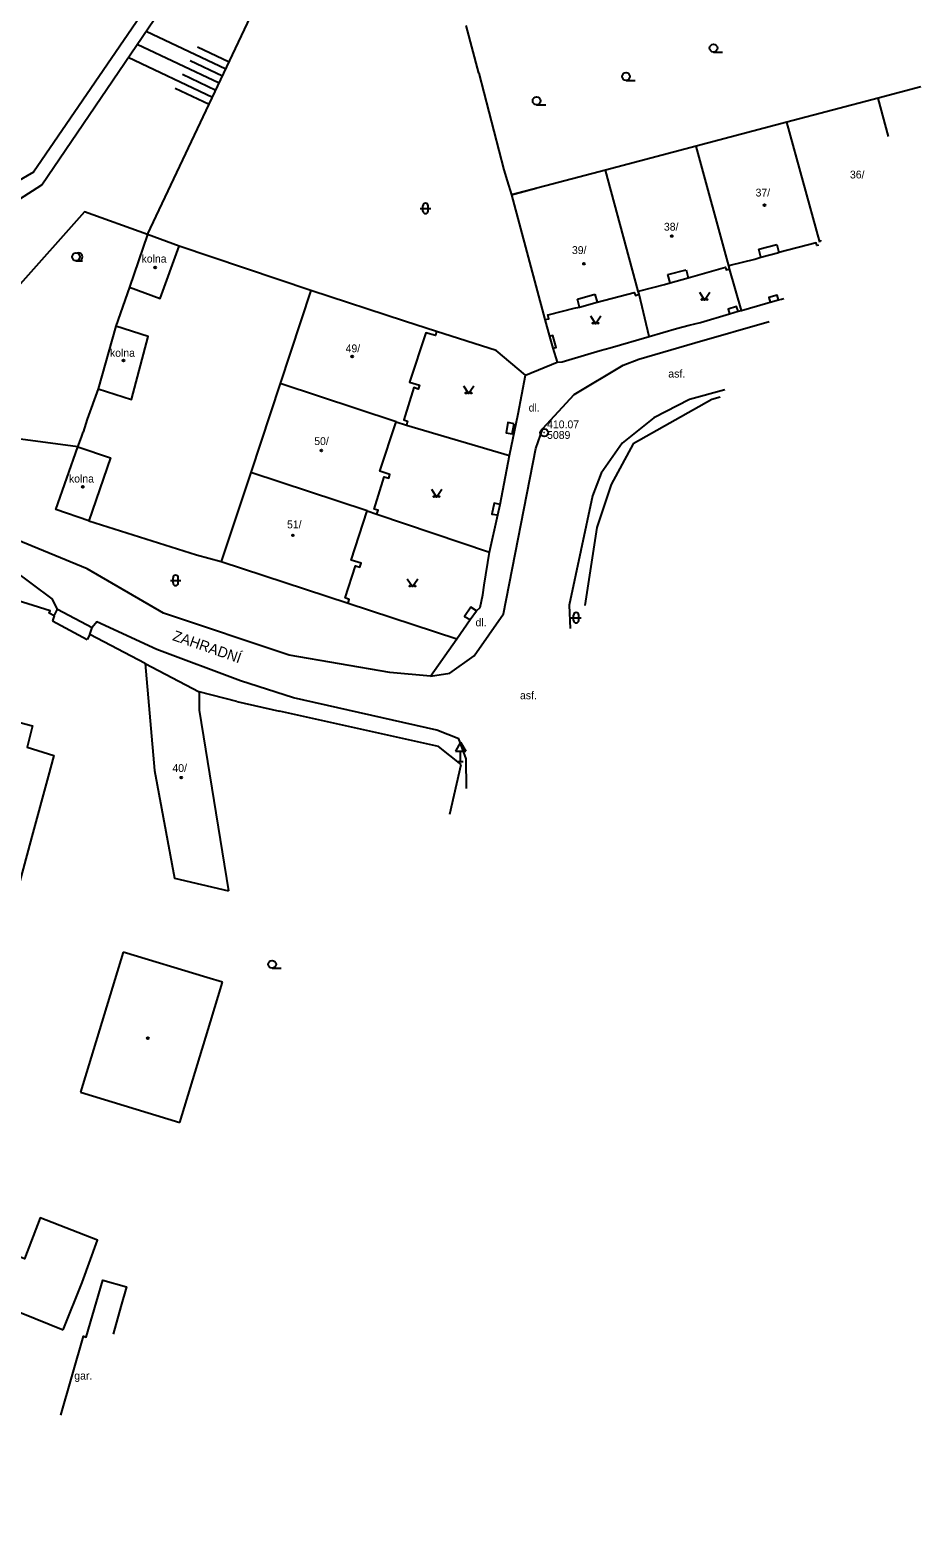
# Model space of a CAD drawing. Extents: x -737488 to -734267, y -1145775 to -1142573.
# Drawn here: x -736865.1 to -736779.7, y -1144915.2 to -1144770.7 of the extents above; entities that cross this region are included whole.
import ezdxf

# ---------------------------------------------------------------- set-up
doc = ezdxf.new("R2010")
doc.units = 0
for name, color, linetype in [('Vrstva 1', 7, 'Continuous'), ('Vrstva 10', 7, 'Continuous'), ('Vrstva 11', 7, 'Continuous'), ('Vrstva 12', 7, 'Continuous'), ('Vrstva 13', 7, 'Continuous'), ('Vrstva 14', 7, 'Continuous'), ('Vrstva 19', 7, 'Continuous'), ('Vrstva 3', 7, 'Continuous'), ('Vrstva 4', 7, 'Continuous'), ('Vrstva 5', 7, 'Continuous'), ('Vrstva 6', 7, 'Continuous'), ('Vrstva 8', 7, 'Continuous'), ('Vrstva 9', 7, 'Continuous')]:
    doc.layers.add(name, color=color, linetype=linetype)

# ---------------------------------------------------------------- blocks, each defined once
blk = doc.blocks.new('1.079')
at = {"layer": 'Vrstva 1'}
for radius in [0.75, 0.001]:
    blk.add_circle((0, -0.001), radius, dxfattribs=at)
blk = doc.blocks.new('3.040')
at = {"layer": 'Vrstva 1'}
blk.add_line((0, -0.75), (1.75, -0.75), dxfattribs=at)
blk.add_circle((0, 0), 0.75, dxfattribs=at)
blk = doc.blocks.new('3.110')
at = {"layer": 'Vrstva 1'}
blk.add_line((0, -0.75), (1.25, -0.75), dxfattribs=at)
blk.add_circle((0, 0), 0.75, dxfattribs=at)
blk.add_arc((0.5, 0), 0.75, 249.4944, 109.0474, dxfattribs=at)
blk = doc.blocks.new('3.140')
at = {"layer": 'Vrstva 1'}
blk.add_lwpolyline([(-1, 1.5), (0, 0), (1, 1.5)], dxfattribs=at)
for centre in [(-0.5, 0.1), (0.5, 0.1)]:
    blk.add_circle(centre, 0.1, dxfattribs=at)
blk = doc.blocks.new('3.160')
at = {"layer": 'Vrstva 1'}
for p, q in [((-1, 0), (1, 0)), ((-0.5, -0.5), (-0.5, 0.5)), ((0.5, -0.5), (0.5, 0.5))]:
    blk.add_line(p, q, dxfattribs=at)
for centre, start, end in [((0, 0.5), 0, 180), ((0, -0.5), 180, 360)]:
    blk.add_arc(centre, 0.5, start, end, dxfattribs=at)
blk = doc.blocks.new('4.020')
at = {"layer": 'Vrstva 1'}
blk.add_circle((0, 0), 0.175, dxfattribs=at)
blk = doc.blocks.new('5.270')
at = {"layer": 'Vrstva 1'}
for p, q in [((0, 3.732), (-1, 2)), ((0, 3.732), (1, 2)), ((-1, 2), (1, 2)), ((-0.5, 0), (0.5, 0)), ((0, 0), (0, 2))]:
    blk.add_line(p, q, dxfattribs=at)

msp = doc.modelspace()

# ---------------------------------------------------------------- linework, layer by layer
at = {"layer": 'Vrstva 10'}
for points in [[(-737157.23, -1144612.91), (-737139.97, -1144630.07), (-737087.28, -1144684.25), (-737074.24, -1144695.65), (-737061.32, -1144701.82), (-737047.37, -1144710.31), (-737029.75, -1144716.98), (-737014.23, -1144719.82), (-736985.3, -1144724.31), (-736947.36, -1144728.54), (-736914.56, -1144733.34), (-736885.96, -1144736.43), (-736848.96, -1144741.06), (-736841.09, -1144741.37), (-736845.82, -1144755.24), (-736853.37, -1144767.68), (-736864.78, -1144784.35), (-736886.96, -1144797.2)], [(-736885.77, -1144799.53), (-736863.97, -1144785.57), (-736852.06, -1144768.02), (-736845.63, -1144757.82), (-736839.46, -1144741.72), (-736833.85, -1144740.76), (-736819.77, -1144737.85)], [(-736826.72, -1144832.66), (-736824.85, -1144832.36), (-736822.52, -1144830.71), (-736819.71, -1144826.67), (-736816.62, -1144810.84), (-736815.93, -1144808.92), (-736812.95, -1144805.66), (-736808.25, -1144802.83), (-736806.75, -1144802.26), (-736801.36, -1144800.69), (-736794.25, -1144798.65)], [(-736817.6, -1144803.79), (-736814.58, -1144802.55)], [(-736798.5, -1144805.21), (-736801.89, -1144806.15), (-736805.31, -1144807.89), (-736808.33, -1144810.32), (-736810.35, -1144813.2), (-736811.19, -1144815.38), (-736813.4, -1144825.86), (-736813.32, -1144828.08)], [(-736826.72, -1144832.66), (-736830.61, -1144832.31), (-736840.28, -1144830.64), (-736852.33, -1144826.62), (-736859.62, -1144822.37), (-736874.24, -1144816.36), (-736880.96, -1144815.92)], [(-736862.48, -1144826.23), (-736862.98, -1144825.23), (-736866.76, -1144822.43), (-736874.46, -1144819.59), (-736880.16, -1144818.92), (-736884.21, -1144819.43), (-736894.52, -1144823.06), (-736901.86, -1144830.06), (-736906.51, -1144840.28), (-736908.98, -1144850.82), (-736911.51, -1144865.17), (-736912.91, -1144881.09), (-736910.68, -1144885.98), (-736901.74, -1144895.69), (-736893.29, -1144902.9), (-736886.85, -1144907.19), (-736879.51, -1144911.23), (-736869.79, -1144915.23)], [(-736862.79, -1144826.86), (-736862.48, -1144826.23)], [(-736862.48, -1144826.23), (-736859.17, -1144827.99)], [(-736859.38, -1144828.65), (-736859.17, -1144827.99)], [(-736823.26, -1144843.42), (-736823.29, -1144840.58), (-736823.99, -1144838.65), (-736826.11, -1144837.82), (-736839.86, -1144834.72), (-736844.94, -1144833.11), (-736852.96, -1144830.08), (-736858.7, -1144827.43), (-736859.17, -1144827.99)], [(-736826.72, -1144832.66), (-736824.19, -1144829.08)]]:
    msp.add_lwpolyline(points, dxfattribs=at)
at = {"layer": 'Vrstva 11'}
msp.add_lwpolyline([(-736860.53, -1144810.66), (-736881.41, -1144807.88), (-736885.77, -1144800.79)], dxfattribs=at)
at = {"layer": 'Vrstva 12'}
for points in [[(-736853.84, -1144790.33), (-736842.01, -1144765.32), (-736835.71, -1144748.55), (-736834.5, -1144742.96), (-736819.77, -1144737.85)], [(-736846.34, -1144774.47), (-736853.99, -1144770.86)], [(-736847.62, -1144777.19), (-736855.69, -1144773.37)], [(-736846.98, -1144775.83), (-736854.84, -1144772.11)], [(-736846.02, -1144773.8), (-736849.04, -1144772.37)], [(-736846.66, -1144775.15), (-736849.76, -1144773.69)], [(-736847.3, -1144776.51), (-736850.49, -1144775)], [(-736847.94, -1144777.86), (-736851.21, -1144776.32)], [(-736853.84, -1144790.33), (-736859.89, -1144788.14), (-736866.31, -1144795.38), (-736885.77, -1144800.79)]]:
    msp.add_lwpolyline(points, dxfattribs=at)
at = {"layer": 'Vrstva 4'}
for points in [[(-736818.95, -1144786.52), (-736815.75, -1144798.47)], [(-736853.84, -1144790.33), (-736855.58, -1144795.37)], [(-736850.81, -1144791.43), (-736853.84, -1144790.33)], [(-736855.58, -1144795.37), (-736852.63, -1144796.44), (-736850.81, -1144791.43)], [(-736795.23, -1144791.73), (-736793.5, -1144791.28)], [(-736795.03, -1144792.5), (-736795.23, -1144791.73)], [(-736795.03, -1144792.5), (-736793.3, -1144792.05)], [(-736793.5, -1144791.28), (-736793.3, -1144792.05)], [(-736789.51, -1144791.33), (-736789.67, -1144791.37), (-736789.74, -1144791.11), (-736793.3, -1144792.05)], [(-736789.41, -1144790.93), (-736789.26, -1144790.89), (-736789.22, -1144790.88)], [(-736789.37, -1144791.1), (-736789.41, -1144790.93)], [(-736802.01, -1144794.49), (-736798.42, -1144793.46), (-736798.36, -1144793.71), (-736798.04, -1144793.61)], [(-736798.12, -1144793.32), (-736797.97, -1144793.27), (-736795.61, -1144792.67), (-736795.03, -1144792.5)], [(-736798.04, -1144793.61), (-736798.12, -1144793.32)], [(-736806.79, -1144795.75), (-736806.64, -1144795.71), (-736804.28, -1144795.1), (-736803.74, -1144794.94)], [(-736803.94, -1144794.17), (-736802.21, -1144793.72)], [(-736803.74, -1144794.94), (-736803.94, -1144794.17)], [(-736803.74, -1144794.94), (-736802.01, -1144794.49)], [(-736802.21, -1144793.72), (-736802.01, -1144794.49)], [(-736838.19, -1144795.68), (-736841.14, -1144804.61)], [(-736826.13, -1144799.62), (-736829.19, -1144798.63), (-736838.19, -1144795.68)], [(-736812.63, -1144796.52), (-736810.95, -1144796.05)], [(-736812.41, -1144797.29), (-736812.63, -1144796.52)], [(-736810.95, -1144796.05), (-736810.73, -1144796.82)], [(-736810.73, -1144796.82), (-736807.17, -1144795.88), (-736807.04, -1144796.16), (-736806.71, -1144796.05)], [(-736806.71, -1144796.05), (-736806.79, -1144795.75)], [(-736815.75, -1144798.47), (-736815.36, -1144798.39), (-736815.46, -1144798.02), (-736815.31, -1144797.98), (-736812.94, -1144797.39), (-736812.41, -1144797.29)], [(-736812.41, -1144797.29), (-736810.73, -1144796.82)], [(-736826.13, -1144799.62), (-736826.22, -1144799.99), (-736827.17, -1144799.74), (-736828.72, -1144804.46), (-736827.77, -1144804.77), (-736827.88, -1144805.13), (-736828.32, -1144805), (-736829.28, -1144808.09), (-736828.93, -1144808.22), (-736829.02, -1144808.58)], [(-736841.14, -1144804.61), (-736843.95, -1144813.13)], [(-736831.86, -1144817.12), (-736831.72, -1144816.74), (-736832.12, -1144816.63), (-736831.16, -1144813.54), (-736830.72, -1144813.67), (-736830.61, -1144813.31), (-736831.56, -1144813), (-736830, -1144808.26)], [(-736830, -1144808.26), (-736829.02, -1144808.58)], [(-736859.49, -1144817.77), (-736862.63, -1144816.69), (-736860.53, -1144810.66)], [(-736860.53, -1144810.66), (-736857.41, -1144811.73), (-736859.49, -1144817.77)], [(-736843.95, -1144813.13), (-736846.77, -1144821.66)], [(-736834.62, -1144825.64), (-736834.51, -1144825.29), (-736834.88, -1144825.15), (-736833.92, -1144822.06), (-736833.48, -1144822.19), (-736833.37, -1144821.83), (-736834.32, -1144821.52), (-736832.77, -1144816.8)], [(-736832.77, -1144816.8), (-736831.86, -1144817.12)], [(-736846.77, -1144821.66), (-736834.62, -1144825.64)], [(-736854.07, -1144831.42), (-736848.88, -1144834.14)]]:
    msp.add_lwpolyline(points, dxfattribs=at)
at = {"layer": 'Vrstva 5'}
for points in [[(-736779.69, -1144776.17), (-736783.79, -1144777.25), (-736792.54, -1144779.56), (-736801.23, -1144781.85), (-736809.92, -1144784.14), (-736818.95, -1144786.52)], [(-736782.78, -1144780.94), (-736783.79, -1144777.25)], [(-736789.41, -1144790.93), (-736792.54, -1144779.56)], [(-736798.12, -1144793.32), (-736801.23, -1144781.85)], [(-736806.79, -1144795.75), (-736809.92, -1144784.14)], [(-736818.95, -1144786.52), (-736816.57, -1144785.88)], [(-736856.88, -1144799.12), (-736858.58, -1144805.1), (-736855.38, -1144806.14), (-736853.8, -1144800.1), (-736856.88, -1144799.12)], [(-736830, -1144808.26), (-736841.14, -1144804.61)], [(-736832.77, -1144816.8), (-736843.95, -1144813.13)], [(-736854.07, -1144831.42), (-736853.19, -1144841.68), (-736851.27, -1144852.02), (-736846.07, -1144853.23)], [(-736872.15, -1144835.37), (-736871.5, -1144835.55), (-736865.95, -1144837.12), (-736864.89, -1144837.42), (-736865.4, -1144839.44), (-736862.82, -1144840.24), (-736863.37, -1144842.28), (-736864.93, -1144848.02), (-736867.19, -1144856.35), (-736876.92, -1144853.35), (-736873.4, -1144840.07), (-736872.15, -1144835.37)], [(-736848.88, -1144834.14), (-736848.9, -1144835.92), (-736846.07, -1144853.23)], [(-736856.17, -1144859.1), (-736860.26, -1144872.53)], [(-736848.17, -1144861.54), (-736856.17, -1144859.1)], [(-736846.67, -1144861.99), (-736848.17, -1144861.54)], [(-736847.82, -1144865.77), (-736846.67, -1144861.99)], [(-736850.76, -1144875.42), (-736847.82, -1144865.77)], [(-736860.26, -1144872.53), (-736850.76, -1144875.42)], [(-736861.95, -1144895.29), (-736860.12, -1144890.75), (-736858.65, -1144886.71), (-736864.13, -1144884.55), (-736865.64, -1144888.49), (-736879.29, -1144883.01), (-736881.03, -1144887.59), (-736879.28, -1144888.3), (-736875.65, -1144889.76), (-736872.71, -1144890.95), (-736861.95, -1144895.29)], [(-736862.16, -1144903.46), (-736860, -1144895.89), (-736859.72, -1144896.01), (-736858.12, -1144890.54), (-736855.87, -1144891.17), (-736856.4, -1144893.06), (-736857.13, -1144895.7)]]:
    msp.add_lwpolyline(points, dxfattribs=at)
at = {"layer": 'Vrstva 9'}
for points in [[(-736822.08, -1144774.86), (-736823.29, -1144770.3)], [(-736822.08, -1144774.86), (-736819.68, -1144784.13)], [(-736819.68, -1144784.13), (-736819.36, -1144785.18)], [(-736819.36, -1144785.18), (-736818.95, -1144786.52)], [(-736838.19, -1144795.68), (-736850.81, -1144791.43)], [(-736796.88, -1144797.6), (-736798.04, -1144793.61)], [(-736855.58, -1144795.37), (-736856.88, -1144799.12)], [(-736805.74, -1144800.11), (-736806.71, -1144796.05)], [(-736793.33, -1144796.59), (-736793.47, -1144796.13), (-736794.27, -1144796.37), (-736794.14, -1144796.8)], [(-736793.33, -1144796.59), (-736793.05, -1144796.53)], [(-736793.05, -1144796.53), (-736792.84, -1144796.46)], [(-736800.83, -1144798.76), (-736798.03, -1144797.92)], [(-736797.22, -1144797.67), (-736797.36, -1144797.22), (-736798.17, -1144797.48), (-736798.03, -1144797.92)], [(-736798.03, -1144797.92), (-736797.22, -1144797.67)], [(-736797.22, -1144797.67), (-736796.88, -1144797.6)], [(-736796.88, -1144797.6), (-736794.35, -1144796.87)], [(-736794.35, -1144796.87), (-736794.14, -1144796.8)], [(-736794.14, -1144796.8), (-736793.33, -1144796.59)], [(-736815.75, -1144798.47), (-736815.3, -1144800.1)], [(-736805.74, -1144800.11), (-736803.13, -1144799.33)], [(-736803.13, -1144799.33), (-736801.92, -1144799)], [(-736801.92, -1144799), (-736800.83, -1144798.76)], [(-736817.6, -1144803.79), (-736820.41, -1144801.43), (-736826.13, -1144799.62)], [(-736814.98, -1144801.23), (-736814.66, -1144801.14), (-736814.98, -1144800.01), (-736815.3, -1144800.1)], [(-736815.3, -1144800.1), (-736814.98, -1144801.23)], [(-736809.47, -1144801.17), (-736805.74, -1144800.11)], [(-736814.98, -1144801.23), (-736814.58, -1144802.55)], [(-736814.09, -1144802.51), (-736811.61, -1144801.8)], [(-736811.61, -1144801.8), (-736810.44, -1144801.45)], [(-736810.44, -1144801.45), (-736809.47, -1144801.17)], [(-736814.58, -1144802.55), (-736814.09, -1144802.51)], [(-736858.58, -1144805.1), (-736859.64, -1144808.01)], [(-736818.3, -1144807.51), (-736817.6, -1144803.79)], [(-736798.95, -1144805.9), (-736799.74, -1144806.12), (-736807.28, -1144810.38), (-736809.4, -1144814.28), (-736810.77, -1144818.39), (-736811.9, -1144825.89)], [(-736859.64, -1144808.01), (-736860.02, -1144809.27)], [(-736819.14, -1144811.5), (-736818.3, -1144807.51)], [(-736860.17, -1144809.73), (-736860.02, -1144809.27)], [(-736829.02, -1144808.58), (-736819.14, -1144811.5)], [(-736818.69, -1144808.48), (-736819.29, -1144808.33), (-736819.47, -1144809.33), (-736818.89, -1144809.42), (-736818.69, -1144808.48)], [(-736860.53, -1144810.66), (-736860.17, -1144809.73)], [(-736820.03, -1144816.19), (-736819.14, -1144811.5)], [(-736820.03, -1144816.19), (-736820.6, -1144816.07), (-736820.83, -1144817.11), (-736820.25, -1144817.19)], [(-736820.25, -1144817.19), (-736820.03, -1144816.19)], [(-736859.49, -1144817.77), (-736849.16, -1144821.02)], [(-736831.86, -1144817.12), (-736821.07, -1144820.78)], [(-736821.07, -1144820.78), (-736820.25, -1144817.19)], [(-736849.16, -1144821.02), (-736846.77, -1144821.66)], [(-736821.57, -1144823.92), (-736821.07, -1144820.78)], [(-736862.79, -1144826.86), (-736863.29, -1144826.62), (-736863.19, -1144826.38), (-736880.04, -1144821.13), (-736889.1, -1144821.66)], [(-736821.69, -1144824.87), (-736821.57, -1144823.92)], [(-736821.96, -1144826.08), (-736821.69, -1144824.87)], [(-736862.79, -1144826.86), (-736862.97, -1144827.34)], [(-736834.62, -1144825.64), (-736824.19, -1144829.08)], [(-736822.31, -1144826.4), (-736822.85, -1144826.04), (-736823.44, -1144826.92), (-736822.9, -1144827.22)], [(-736822.9, -1144827.22), (-736822.31, -1144826.4)], [(-736822.31, -1144826.4), (-736821.96, -1144826.08)], [(-736862.97, -1144827.34), (-736859.65, -1144829.13)], [(-736824.19, -1144829.08), (-736822.9, -1144827.22)], [(-736859.38, -1144828.65), (-736859.65, -1144829.13)], [(-736854.07, -1144831.42), (-736859.38, -1144828.65)], [(-736845.28, -1144835.07), (-736848.88, -1144834.14)], [(-736845.28, -1144835.07), (-736841.18, -1144835.99)], [(-736823.77, -1144841.11), (-736825.94, -1144839.4), (-736841.18, -1144835.99)], [(-736824.85, -1144845.87), (-736823.77, -1144841.11)]]:
    msp.add_lwpolyline(points, dxfattribs=at)

# ---------------------------------------------------------------- block references
at = {"layer": 'Vrstva 1', "xscale": 0.5, "yscale": 0.5}
msp.add_blockref('1.079', (-736815.81, -1144809.31), dxfattribs=at)
at = {"layer": 'Vrstva 3', "xscale": 0.5, "yscale": 0.5}
for name, p in [('3.040', (-736799.58, -1144772.46)), ('3.040', (-736807.96, -1144775.18)), ('3.040', (-736816.54, -1144777.51)), ('3.160', (-736827.19, -1144787.82)), ('3.110', (-736860.71, -1144792.46)), ('3.140', (-736800.43, -1144796.6)), ('3.140', (-736810.88, -1144798.88)), ('3.140', (-736823.06, -1144805.56)), ('3.140', (-736826.13, -1144815.49)), ('3.160', (-736851.15, -1144823.47)), ('3.140', (-736828.44, -1144824.07)), ('3.160', (-736812.75, -1144827.05)), ('3.040', (-736841.9, -1144860.26))]:
    msp.add_blockref(name, p, dxfattribs=at)
at = {"layer": 'Vrstva 8', "xscale": 0.5, "yscale": 0.5}
for p in [(-736794.68, -1144787.51), (-736803.58, -1144790.47), (-736853.11, -1144793.48), (-736812, -1144793.12), (-736856.15, -1144802.39), (-736834.23, -1144802.01), (-736837.18, -1144811.02), (-736860.06, -1144814.5), (-736839.9, -1144819.15), (-736850.61, -1144842.37), (-736853.81, -1144867.34)]:
    msp.add_blockref('4.020', p, dxfattribs=at)
at = {"layer": 'Vrstva 9', "xscale": 0.5, "yscale": 0.5}
msp.add_blockref('5.270', (-736823.82, -1144840.83), dxfattribs=at)

# ---------------------------------------------------------------- texts
at = {"layer": 'Vrstva 13'}
msp.add_text('ZAHRADNÍ', height=1, rotation=340.84, dxfattribs=at).set_placement((-736851.52, -1144829.18))
at = {"layer": 'Vrstva 14'}
for s, p in [('kolna', (-736854.42, -1144793.01)), ('kolna', (-736857.45, -1144802.04)), ('asf.', (-736803.91, -1144804.03)), ('dl.', (-736817.3, -1144807.29)), ('kolna', (-736861.38, -1144814.09)), ('dl.', (-736822.4, -1144827.87)), ('asf.', (-736818.13, -1144834.86)), ('gar.', (-736860.87, -1144900.06))]:
    msp.add_text(s, height=0.75, dxfattribs=at).set_placement(p)
at = {"layer": 'Vrstva 19'}
for s, p in [(' 410.07', (-736815.81, -1144808.89)), (' 5089', (-736815.81, -1144809.91))]:
    msp.add_text(s, height=0.75, dxfattribs=at).set_placement(p)
at = {"layer": 'Vrstva 6'}
for s, p in [('36/', (-736786.49, -1144784.95)), ('37/', (-736795.54, -1144786.68)), ('38/', (-736804.33, -1144789.95)), ('39/', (-736813.15, -1144792.19)), ('49/', (-736834.85, -1144801.61)), ('50/', (-736837.86, -1144810.5)), ('51/', (-736840.47, -1144818.48)), ('40/', (-736851.46, -1144841.83))]:
    msp.add_text(s, height=0.75, dxfattribs=at).set_placement(p)

doc.saveas('drawing.dxf')
